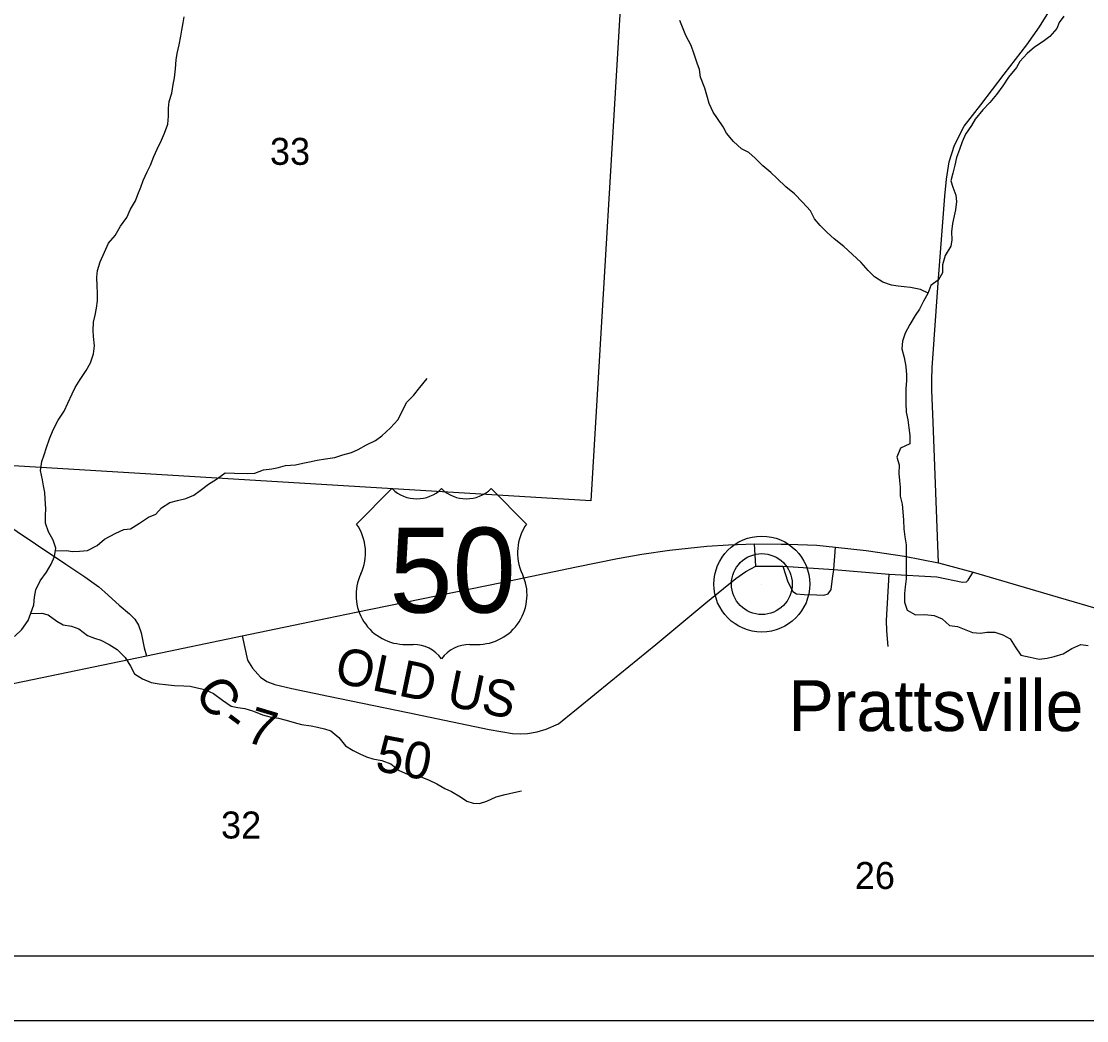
# Model space of a CAD drawing. Extents: x 0 to 34, y 0 to 22.
# Drawn here: x 26.642 to 28.295, y 14 to 15.55 of the extents above; entities that cross this region are included whole.
import ezdxf

# ---------------------------------------------------------------- set-up
doc = ezdxf.new("R2010")
doc.units = 0
for name, color, linetype in [('GM_X_County_Road', 7, 'Continuous'), ('GM_X_County_Road_Text', 7, 'Continuous'), ('GM_X_Minor_River', 7, 'Continuous'), ('GM_X_Section', 7, 'Continuous'), ('GM_X_Section_Text', 7, 'Continuous'), ('GM_X_State_Route', 7, 'Continuous'), ('GM_X_Township_Road', 7, 'Continuous'), ('GM_X_Unincorporated', 7, 'Continuous'), ('GM_X_Unincorporated_Location', 7, 'Continuous'), ('GM_X_Unincorporated_Text', 7, 'Continuous'), ('GM_X_US_Location', 7, 'Continuous'), ('GM_X_US_Route', 7, 'Continuous'), ('GM_X_US_Shield', 7, 'Continuous'), ('SH_Data', 7, 'Continuous')]:
    doc.layers.add(name, color=color, linetype=linetype)

msp = doc.modelspace()

# ---------------------------------------------------------------- linework, layer by layer
at = {"layer": 'GM_X_County_Road'}
msp.add_line((26.8368, 14.566), (26.9849, 14.597), dxfattribs=at)
for points in [[(26.5363, 14.8248), (26.5379, 14.8237), (26.5577, 14.8115), (26.6069, 14.7782), (26.6644, 14.7396), (26.7114, 14.7084), (26.7412, 14.6887), (26.7627, 14.6728), (26.7722, 14.6646), (26.7942, 14.6446), (26.8101, 14.6313), (26.8183, 14.6228), (26.8242, 14.6133), (26.8285, 14.6018), (26.8331, 14.5785), (26.8368, 14.566)], [(26.9849, 14.597), (26.9935, 14.5594), (27.0011, 14.5466), (27.0135, 14.5328), (27.0231, 14.5262), (27.036, 14.5213), (27.0623, 14.5154), (27.1188, 14.5032), (27.2419, 14.4783), (27.3684, 14.4516), (27.4043, 14.4456), (27.4177, 14.445), (27.4279, 14.4456), (27.4426, 14.4481), (27.4569, 14.4524), (27.4757, 14.4607), (27.4875, 14.4699), (27.5065, 14.4854), (27.5571, 14.5266), (27.6269, 14.5838), (27.7045, 14.6484), (27.7513, 14.686), (27.7666, 14.697), (27.7821, 14.7052), (27.8238, 14.7051), (27.9032, 14.6999), (27.9889, 14.6929), (28.0632, 14.6887), (28.1027, 14.6804), (28.1088, 14.6806), (28.1114, 14.6833), (28.1148, 14.6885), (28.1194, 14.6956)]]:
    msp.add_lwpolyline(points, dxfattribs=at)
at = {"layer": 'GM_X_Minor_River'}
for points in [[(26.8803, 15.4628), (26.8818, 15.4768), (26.8829, 15.4904), (26.8844, 15.5003), (26.8874, 15.5139), (26.89, 15.5272), (26.8914, 15.5367), (26.8937, 15.5477), (26.8952, 15.5572)], [(28.2598, 15.5582), (28.253, 15.5484), (28.2489, 15.5389), (28.2383, 15.5267), (28.2277, 15.5191), (28.2145, 15.51), (28.2032, 15.5005), (28.1919, 15.4879), (28.1866, 15.4784), (28.1741, 15.4637)], [(27.6961, 15.4634), (27.6945, 15.4757), (27.6911, 15.4852), (27.6865, 15.4992), (27.6819, 15.5128), (27.6735, 15.528), (27.6693, 15.5386), (27.6644, 15.5515)], [(26.6316, 14.596), (26.6433, 14.607), (26.6528, 14.6206), (26.6574, 14.6324), (26.6619, 14.6449), (26.6631, 14.657), (26.665, 14.6683), (26.6718, 14.6824), (26.6817, 14.696), (26.6885, 14.7081), (26.6938, 14.7202), (26.6957, 14.7331), (26.692, 14.7452), (26.6848, 14.7581), (26.6799, 14.7718), (26.6799, 14.7839), (26.6803, 14.7938), (26.6796, 14.8093), (26.6788, 14.8192), (26.677, 14.8298), (26.6755, 14.8392), (26.6721, 14.8536), (26.674, 14.8673), (26.6778, 14.8779), (26.6816, 14.8889), (26.6862, 14.9025), (26.6919, 14.9165), (26.6994, 14.9313), (26.7089, 14.9457), (26.7146, 14.9578), (26.7211, 14.9722), (26.726, 14.9824), (26.7336, 14.9945), (26.7431, 15.0085), (26.7499, 15.0207), (26.7545, 15.0343), (26.756, 15.0468), (26.7545, 15.0612), (26.7538, 15.0707), (26.7545, 15.0836), (26.7568, 15.0945), (26.7591, 15.1052), (26.7606, 15.1169), (26.7607, 15.129), (26.7599, 15.1393), (26.7596, 15.1533), (26.7607, 15.1639), (26.7645, 15.1771), (26.7714, 15.1919), (26.7778, 15.2059), (26.788, 15.218), (26.7964, 15.2324), (26.8059, 15.2457), (26.8119, 15.2589), (26.8195, 15.2718), (26.8233, 15.2817), (26.8279, 15.293), (26.8317, 15.3032), (26.8377, 15.3169), (26.8427, 15.3271), (26.848, 15.3404), (26.8533, 15.3521), (26.8601, 15.3661), (26.8647, 15.3767), (26.8696, 15.3907), (26.8708, 15.4032), (26.8708, 15.4157), (26.872, 15.426), (26.8761, 15.4388), (26.8781, 15.4521), (26.8803, 15.4628)], [(28.0494, 15.1288), (28.0378, 15.1343), (28.0223, 15.1374), (28.0125, 15.1385), (28.0027, 15.1393), (27.9925, 15.1408), (27.9792, 15.1458), (27.966, 15.1541), (27.9562, 15.1636), (27.9453, 15.1761), (27.9317, 15.189), (27.9188, 15.2008), (27.9037, 15.2126), (27.8928, 15.2228), (27.8818, 15.2335), (27.8731, 15.2437), (27.8667, 15.2562), (27.8543, 15.2699), (27.8422, 15.2828), (27.8286, 15.2934), (27.815, 15.3063), (27.8052, 15.3158), (27.7931, 15.3261), (27.781, 15.3378), (27.7712, 15.3466), (27.7598, 15.3523), (27.7474, 15.3636), (27.7364, 15.3765), (27.7312, 15.3868), (27.7225, 15.3993), (27.7161, 15.4095), (27.7097, 15.4228), (27.707, 15.4323), (27.7029, 15.4463), (27.6961, 15.4634)], [(28.1741, 15.4637), (28.1651, 15.4502), (28.1556, 15.4369), (28.1453, 15.4241), (28.1344, 15.4127), (28.1222, 15.3987), (28.1165, 15.3885), (28.1074, 15.3752), (28.1025, 15.3631), (28.0983, 15.3514), (28.0934, 15.3392), (28.0907, 15.3271), (28.0877, 15.3146), (28.0846, 15.3029), (28.0876, 15.293), (28.0922, 15.2805), (28.0933, 15.2707), (28.0921, 15.2578), (28.0898, 15.2483), (28.0872, 15.2366), (28.0856, 15.2237), (28.0864, 15.2115), (28.0849, 15.2017), (28.0761, 15.1869), (28.0719, 15.1725), (28.0715, 15.16), (28.0655, 15.1494), (28.0537, 15.1407), (28.0492, 15.1282), (28.0424, 15.1161), (28.0359, 15.1036), (28.0291, 15.0938), (28.0211, 15.0798), (28.0139, 15.0665), (28.0097, 15.054), (28.0086, 15.0423), (28.0123, 15.0286), (28.015, 15.015), (28.0157, 15.0021), (28.0157, 14.9926), (28.0149, 14.9805), (28.0149, 14.9577), (28.0156, 14.9441), (28.0182, 14.932), (28.0193, 14.9198), (28.0208, 14.9077), (28.0208, 14.8948), (28.0068, 14.888), (28.0007, 14.8744), (28.0045, 14.8623), (28.0041, 14.8486), (28.0048, 14.838), (28.006, 14.8274), (28.0063, 14.8137), (28.0089, 14.8012), (28.0104, 14.7891), (28.0112, 14.7762), (28.0119, 14.763), (28.0134, 14.7508), (28.0153, 14.7383), (28.0156, 14.7251), (28.0152, 14.7114), (28.0156, 14.6993), (28.0152, 14.6856), (28.0136, 14.6728), (28.0129, 14.6625), (28.0128, 14.6493), (28.017, 14.6368), (28.0298, 14.6295), (28.0442, 14.6299), (28.0586, 14.6287), (28.071, 14.6234), (28.0828, 14.6132), (28.0952, 14.6116), (28.1081, 14.6063), (28.1183, 14.6021), (28.1308, 14.601), (28.1406, 14.6028), (28.1531, 14.6028), (28.1652, 14.5986), (28.1765, 14.5926), (28.1844, 14.58), (28.1935, 14.5668), (28.2079, 14.5637), (28.2215, 14.5607), (28.2343, 14.5625), (28.2449, 14.5648), (28.2589, 14.5693), (28.2722, 14.5773), (28.2862, 14.5833), (28.2979, 14.5821)], [(26.6951, 14.729), (26.712, 14.7293), (26.7222, 14.7278), (26.7328, 14.7281), (26.7453, 14.7296), (26.76, 14.7372), (26.7714, 14.747), (26.7892, 14.7561), (26.8013, 14.7617), (26.8119, 14.7632), (26.8259, 14.7719), (26.8395, 14.781), (26.8512, 14.7859), (26.86, 14.7958), (26.8728, 14.8037), (26.8846, 14.8067), (26.8978, 14.8101), (26.9099, 14.815), (26.9201, 14.8222), (26.9326, 14.8324), (26.9455, 14.84), (26.9588, 14.8498), (26.9731, 14.8494), (26.9935, 14.8486), (27.0045, 14.8494), (27.0181, 14.8543), (27.031, 14.8558), (27.0416, 14.858), (27.0522, 14.861), (27.0677, 14.8625), (27.0794, 14.8648), (27.0896, 14.8667), (27.1017, 14.8693), (27.1142, 14.8716), (27.129, 14.8738), (27.1411, 14.8776), (27.1547, 14.8813), (27.1653, 14.8859), (27.1778, 14.8931), (27.1918, 14.9002), (27.2017, 14.9074), (27.2153, 14.9195), (27.2267, 14.932), (27.2331, 14.9449), (27.2399, 14.9589), (27.2509, 14.9699), (27.2608, 14.9824), (27.2721, 14.996)], [(26.6572, 14.6318), (26.6744, 14.6319), (26.6842, 14.6297), (26.6974, 14.6198), (26.7072, 14.6141), (26.7201, 14.6122), (26.7318, 14.6076), (26.745, 14.5974), (26.756, 14.5932), (26.7658, 14.5905), (26.7787, 14.5837), (26.7911, 14.5757), (26.8036, 14.5635), (26.8119, 14.5499), (26.8179, 14.5381), (26.8304, 14.5302), (26.844, 14.5244), (26.8561, 14.5225), (26.8659, 14.5214), (26.8803, 14.5202), (26.8943, 14.5194), (26.9045, 14.519), (26.9151, 14.5164), (26.9272, 14.5137), (26.9408, 14.5076), (26.9548, 14.4974), (26.968, 14.4879), (26.9782, 14.486), (26.9892, 14.4841), (27.0028, 14.4802), (27.0164, 14.4742), (27.03, 14.4707), (27.0413, 14.4692), (27.0534, 14.4662), (27.0655, 14.4627), (27.0772, 14.4593), (27.092, 14.4574), (27.1022, 14.4551), (27.1128, 14.4528), (27.1226, 14.4494), (27.1351, 14.4391), (27.1456, 14.4266), (27.1574, 14.419), (27.1676, 14.4137), (27.1778, 14.4091), (27.1876, 14.4061), (27.2016, 14.4034), (27.2159, 14.3984), (27.2288, 14.3882), (27.2416, 14.3825), (27.2515, 14.3806), (27.2639, 14.3775), (27.2753, 14.3733), (27.287, 14.3673), (27.2995, 14.36), (27.3097, 14.3555), (27.3236, 14.3471), (27.3335, 14.3403), (27.3433, 14.3376), (27.3531, 14.3368), (27.3645, 14.3406), (27.3792, 14.347), (27.3932, 14.3508), (27.4065, 14.3538), (27.4186, 14.3568)]]:
    msp.add_lwpolyline(points, dxfattribs=at)
at = {"layer": 'GM_X_Section'}
msp.add_lwpolyline([(26.6015, 15.9112), (27.5892, 15.8592), (27.5781, 15.6831), (27.5261, 14.8062), (26.5271, 14.8668)], close=True, dxfattribs=at)
at = {"layer": 'GM_X_State_Route'}
msp.add_lwpolyline([(28.0654, 14.71), (28.0574, 14.9285), (28.0552, 14.9777), (28.0552, 14.9946), (28.0558, 15.0128), (28.0651, 15.1448), (28.0753, 15.2788), (28.0779, 15.3056), (28.0823, 15.3321), (28.0901, 15.3582), (28.1055, 15.3877), (28.131, 15.4208), (28.1674, 15.4684), (28.2025, 15.514), (28.222, 15.5416), (28.2447, 15.5773)], dxfattribs=at)
at = {"layer": 'GM_X_Township_Road'}
for p, q in [((27.7821, 14.7052), (27.7799, 14.7398)), ((27.9032, 14.6999), (27.9057, 14.7347))]:
    msp.add_line(p, q, dxfattribs=at)
for points in [[(27.8238, 14.7051), (27.8315, 14.6806), (27.8393, 14.666), (27.8452, 14.6623), (27.857, 14.661), (27.8767, 14.6605), (27.8877, 14.66), (27.8944, 14.6621), (27.8988, 14.6691), (27.9009, 14.6858), (27.9032, 14.6999)], [(27.9876, 14.5806), (27.9852, 14.6048), (27.9847, 14.621), (27.9889, 14.6929)]]:
    msp.add_lwpolyline(points, dxfattribs=at)
at = {"layer": 'GM_X_Unincorporated'}
for radius in [0.0744, 0.0472]:
    msp.add_circle((27.7914, 14.6773), radius, dxfattribs=at)
at = {"layer": 'GM_X_Unincorporated_Location'}
msp.add_line((27.7914, 14.6773), (27.7914, 14.6773), dxfattribs=at)
at = {"layer": 'GM_X_US_Route'}
msp.add_line((26.8368, 14.566), (26.9849, 14.597), dxfattribs=at)
for points in [[(26.9849, 14.597), (27.117, 14.6242), (27.1621, 14.6337), (27.3875, 14.6795), (27.504, 14.7039), (27.5675, 14.717), (27.6054, 14.7239), (27.6479, 14.73), (27.7062, 14.7362), (27.7397, 14.7382), (27.7799, 14.7398), (27.8215, 14.7394), (27.8329, 14.7394), (27.8767, 14.7374), (27.9057, 14.7347), (27.9532, 14.7295), (28.0128, 14.7204), (28.0654, 14.71)], [(28.0654, 14.71), (28.1194, 14.6956), (28.251, 14.6571), (28.322, 14.6364)], [(25.4058, 14.3985), (25.4796, 14.402), (25.5747, 14.4056), (25.7283, 14.4124), (25.8924, 14.4195), (25.9975, 14.4238), (26.0336, 14.426), (26.0697, 14.4283), (26.0955, 14.4302), (26.1463, 14.4343), (26.1985, 14.4405), (26.2856, 14.4541), (26.3433, 14.4637), (26.4907, 14.4943), (26.4916, 14.4945), (26.6321, 14.5235), (26.8368, 14.566)]]:
    msp.add_lwpolyline(points, dxfattribs=at)
at = {"layer": 'GM_X_US_Shield'}
for p, q in [((27.2175, 14.8253), (27.1626, 14.7703)), ((27.4262, 14.7703), (27.3713, 14.8253)), ((27.2395, 14.5836), (27.2505, 14.5836)), ((27.3384, 14.5836), (27.3493, 14.5836))]:
    msp.add_line(p, q, dxfattribs=at)
for centre, radius, start, end in [((27.256, 14.8645), 0.0549, 225.573, 314.427), ((27.3329, 14.8645), 0.0549, 225.573, 314.427), ((27.0996, 14.7262), 0.0769, 334.5471, 35.0009), ((27.4892, 14.7262), 0.0769, 144.9991, 205.4529), ((27.2386, 14.6605), 0.0769, 154.8319, 270.6383), ((27.3502, 14.6605), 0.0769, 269.3617, 25.1681), ((27.2505, 14.5286), 0.0549, 36.8699, 90), ((27.3384, 14.5286), 0.0549, 90, 143.1301)]:
    msp.add_arc(centre, radius, start, end, dxfattribs=at)
at = {"layer": 'SH_Data'}
for points in [[(23.4167, 21), (30.4167, 21), (30.4167, 14), (23.4167, 14)], [(23.5167, 20.9), (30.3167, 20.9), (30.3167, 14.1), (23.5167, 14.1)]]:
    msp.add_lwpolyline(points, close=True, dxfattribs=at)

# ---------------------------------------------------------------- texts
at = {"layer": 'GM_X_County_Road_Text'}
for s, height, rotation, p in [('OLD US', 0.05682, 348.2393, (27.1265, 14.5253)), ('C', 0.0568, 305.3054, (26.9093, 14.5092)), ('7', 0.0568, 343.2986, (26.9878, 14.4337)), ('-', 0.0568, 323.422, (26.9499, 14.4572)), ('50', 0.05682, 348.9577, (27.1897, 14.3884))]:
    msp.add_text(s, height=height, rotation=rotation, dxfattribs=at).set_placement(p)
at = {"layer": 'GM_X_Section_Text'}
for s, p in [('33', (27.0282, 15.3276)), ('32', (26.9523, 14.2826)), ('26', (27.9357, 14.2043))]:
    msp.add_text(s, height=0.04186, rotation=0, dxfattribs=at).set_placement(p)
at = {"layer": 'GM_X_Unincorporated_Text'}
msp.add_text('Prattsville', height=0.078977, rotation=0, dxfattribs=at).set_placement((27.8327, 14.4492))
at = {"layer": 'GM_X_US_Location'}
for s, p in [('0', (27.2943, 14.6979)), ('/', (27.2944, 14.6979))]:
    msp.add_text(s, height=0.000189, dxfattribs=at).set_placement(p)
msp.add_text('50', height=0.000189, rotation=0, dxfattribs=at).set_placement((27.2552, 14.6587))
at = {"layer": 'GM_X_US_Shield'}
msp.add_text('50', height=0.13184, dxfattribs=at).set_placement((27.2135, 14.633))

doc.saveas('drawing.dxf')
